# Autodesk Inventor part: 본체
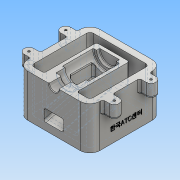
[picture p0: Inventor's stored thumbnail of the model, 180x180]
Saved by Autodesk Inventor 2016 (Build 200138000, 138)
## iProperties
Created: 2018-01
Part Number: 본체
Material: 알루미늄 6061
Document SubType Name: Modeling
Designer: Administrator
Density: 2.7 g/cm^3
Appearance: 알루미늄 - 평지
Mass: 994.889 g
Surface Area: 835.455 cm^2
Volume: 368.478 cm^3
Author: Administrator
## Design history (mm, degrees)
sketch "스케치1"
  geometry: L1 (0, 59.655)-(110, 59.655); L2 (110, 59.655)-(110, -50.345); L3 (110, -50.345)-(0, -50.345); L4 (0, -50.345)-(0, 59.655); 1 further point
  constraints: 8 end point, 2 parallel, 1 horizontal, 1 perpendicular
  dimensions: "d0" = 110 distance of L1.start L1.end; "d1" = 110 distance of L1.end L2.end
extrude "돌출1" new body sketch "스케치1" distance "d2" = 65; taper "d3" = 0 deg
sketch "스케치2"
  geometry: L1 (0, 59.655)-(0, -50.345) reference; L2 (0, -50.345)-(110, -50.345) reference; L3 (0, -15.845)-(-10, -15.845); L4 (0, -30.845)-(-10, -30.845); L5 (-10, -15.845)-(-10, -30.845); A1 r 7.5 centre (-10, -23.345) between (-10, -15.845) and (-10, -30.845); 1 further point
  constraints: 6 end point, 2 horizontal, 2 point on circle, 2 point on line, 1 centre point, 1 midpoint, 1 vertical
  dimensions: "d4" = 7.5 radius of A1; "d5" = 10 distance of L4.start L4.end; "d6" = 27 distance from line of L2 A1.centre
extrude "돌출2" join sketch "스케치2" distance "d7" = 20; taper "d8" = 0 deg
node "작업 평면1"
sketch "스케치3"
  geometry: L1 (0, -50.345)-(110, -50.345) reference; L2 (55, -50.345)-(55, 34.655); L3 (47.5, -50.345)-(47.5, -31.345); L4 (47.5, -31.345)-(39, -31.345); L5 (39, -31.345)-(39, -17.345); L6 (39, -17.345)-(35, -17.345); L7 (35, -17.345)-(35, 29.655); L8 (35, 29.655)-(40, 29.655); L9 (40, 29.655)-(40, 34.655); L10 (40, 34.655)-(55, 34.655); 1 further point
  constraints: 18 end point, 7 perpendicular, 2 vertical, 1 midpoint, 1 point on line
  dimensions: "d13" = 15 diameter of L3 L2; "d14" = 32 diameter of L5 L2; "d15" = 40 diameter of L7 L2; "d16" = 30 diameter of L9 L2; "d17" = 19 distance of L3.start L3.end; "d18" = 14 distance of L4.end L5.end; "d19" = 47 distance of L6.end L7.end; "d20" = 5 distance of L8.end L9.end
revolve "회전1" sketch "스케치3" stored, may be unused: angle "d21" = 90 deg
sketch "스케치5"
  geometry: L1 (110, -15.845)-(110, 25.155) reference; L2 (110, 59.655)-(0, 59.655) reference; L3 (0, 25.155)-(0, -15.845) reference; L4 (0, -50.345)-(47.5, -50.345) reference; L5 (10, -40.345)-(10, 49.655); L6 (10, 49.655)-(100, 49.655); L7 (100, 49.655)-(100, -40.345); L8 (100, -40.345)-(80, -40.345); L9 (80, -40.345)-(80, 39.655); L10 (80, 39.655)-(30, 39.655); L11 (30, 39.655)-(30, -40.345); L12 (30, -40.345)-(10, -40.345); 1 further point
  constraints: 16 end point, 7 perpendicular, 1 point on line, 1 vertical
  dimensions: "d22" = 20 distance between parallel lines of L2 L10; "d23" = 10 distance between parallel lines of L2 L6; "d24" = 10 distance between parallel lines of L1 L7; "d25" = 10 distance between parallel lines of L3 L5; "d26" = 30 distance between parallel lines of L3 L11; "d27" = 30 distance between parallel lines of L1 L9; "d28" = 10 distance between parallel lines of L4 L12
extrude "돌출3" cut sketch "스케치5" stored distance "d29" = 20; taper "d30" = 0 deg
sketch "스케치7"
  geometry: L1 (-50.345, 0)-(-50.345, 65) reference; L2 (-50.345, 29.061)-(-12.345, 39.243); L3 (-12.345, 39.243)-(24.655, 39.243); L4 (24.655, 39.243)-(24.655, 31.157); L5 (24.655, 31.157)-(-50.345, 11.061); L6 (-40.345, 65)-(49.655, 65) reference; L7 (49.655, 0)-(-40.345, 0) reference; L8 (59.655, 0)-(59.655, 65) reference; L9 (39.655, 65)-(39.655, 30); L10 (39.655, 30)-(-31.623, 10.901); L11 (-50.345, 0)-(59.655, 0) reference; 1 further point
  constraints: 12 end point, 3 point on line, 2 parallel, 2 perpendicular, 1 vertical
  dimensions: "d33" = 18 distance of L5.end L2.start; "d34" = 37 distance of L2.end L3.end; "d35" = 75 deg angle of L1 L2; "d36" = 38 distance from line of L2.end L1; "d69" = 20 distance between parallel lines of L9 L8; "d70" = 30 distance from line of L11 L9.end; "d71" = 5 distance between parallel lines of L5 L10
extrude "돌출4" cut sketch "스케치7" stored distance "d40" = 30; taper "d42" = 0 deg; dims "d41" = 10, "d43" = 0
sketch "스케치8"
  geometry: L1 (40, -12.345)-(40, 24.655) reference; L2 (70, -12.345)-(70, -50.345) reference; L3 (40, 24.655)-(70, 24.655); L4 (70, 24.655)-(70, -12.345); L5 (70, -12.345)-(40, -12.345); L6 (40, -12.345)-(40, 24.655); 1 further point
  constraints: 8 end point, 2 parallel, 1 horizontal, 1 perpendicular
extrude "돌출5" cut sketch "스케치8" stored distance "d44" = 30; taper "d45" = 0 deg
hole "구멍1" diameter "d48" = 3.242; stored, may be unused: countersink angle "d52" = 90 deg, drill point angle "d54" = 118 deg; dims "d46" = 10, "d47" = 10, "d49" = 9, "d50" = 4, "d51" = 2, "d53" = 11
sketch "스케치10"
  geometry: L1 (65, 0)-(65, 80) reference; L2 (53.939, -10)-(33.843, 65) reference; L3 (0, 80.5)-(0, 65.5) reference; L4 (56.436, 0)-(35, 80); L5 (35, 80)-(0, 80); L6 (65, 100)-(0, 100) reference; L7 (65, 90)-(65, 0) reference; L8 (56.436, 0)-(65, 0); L9 (65, -10)-(0, -10) reference; L10 (0, 80)-(65, 80) reference; L11 (35, 80)-(65, 80); L12 (65, 80)-(65, 0); 1 further point
  constraints: 10 end point, 2 perpendicular, 2 point on line, 1 collinear, 1 parallel
  dimensions: "d62" = 20 distance from line of L6 L5.end; "d63" = 30 distance from line of L7 L4.end; "d64" = 10 distance between parallel lines of L9 L8
extrude "돌출6" cut sketch "스케치10" stored distance "d65" = 30; taper "d66" = 0 deg
sketch "스케치11"
  geometry: L1 (0, 0)-(-65, 0) reference; L2 (0, 110)-(0, 0) reference; 2 further points
  constraints: 1 other
  dimensions: "d72" = 55 distance from line of L1 point (-20, 55); "d73" = 20 distance from line of L2 point (-20, 55)
feature "엠보싱1" sketch "스케치11" dims "d0" = 110, "d1" = 110, "d12" = 55, "d74" = 0.5, "d75" = 0
fillet "모깎기1" dims "d76" = 5, "d77" = 3, "d78" = 1, "d85" = 15
chamfer "모따기1" distance "d79" = 1; stored, may be unused: second distance "d80" = 2, angle "d81" = 45 deg
chamfer "모따기2" distance "d82" = 1; stored, may be unused: second distance "d83" = 2, angle "d84" = 45 deg
node "솔리드1"
pattern_linear "직사각형 패턴1" dims "d11" = 56
mirror "대칭1"
pattern_linear "직사각형 패턴2" dims "d57" = 56
